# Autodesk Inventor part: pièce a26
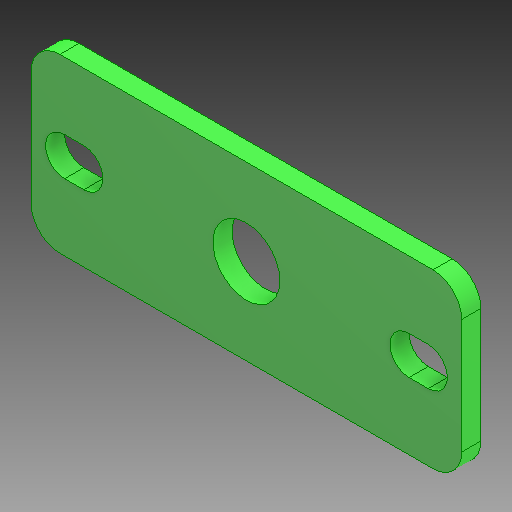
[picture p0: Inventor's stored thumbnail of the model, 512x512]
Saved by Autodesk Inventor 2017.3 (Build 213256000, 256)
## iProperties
Created: 2007-12
Part Number: pièce a26
Material: solidworks materials|PVC 0.007 plastifié|45
Document SubType Name: Modeling
Designer: ficho
Density: 1.29 g/cm^3
Appearance: 0,255,01
Author: ficho
Sending System: SolidWorks 2009
Last Author: christophe
Last Saved: 2011-02-10
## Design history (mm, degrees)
feature "Enlèv. mat.-Extru.1"
node "Solide1"
